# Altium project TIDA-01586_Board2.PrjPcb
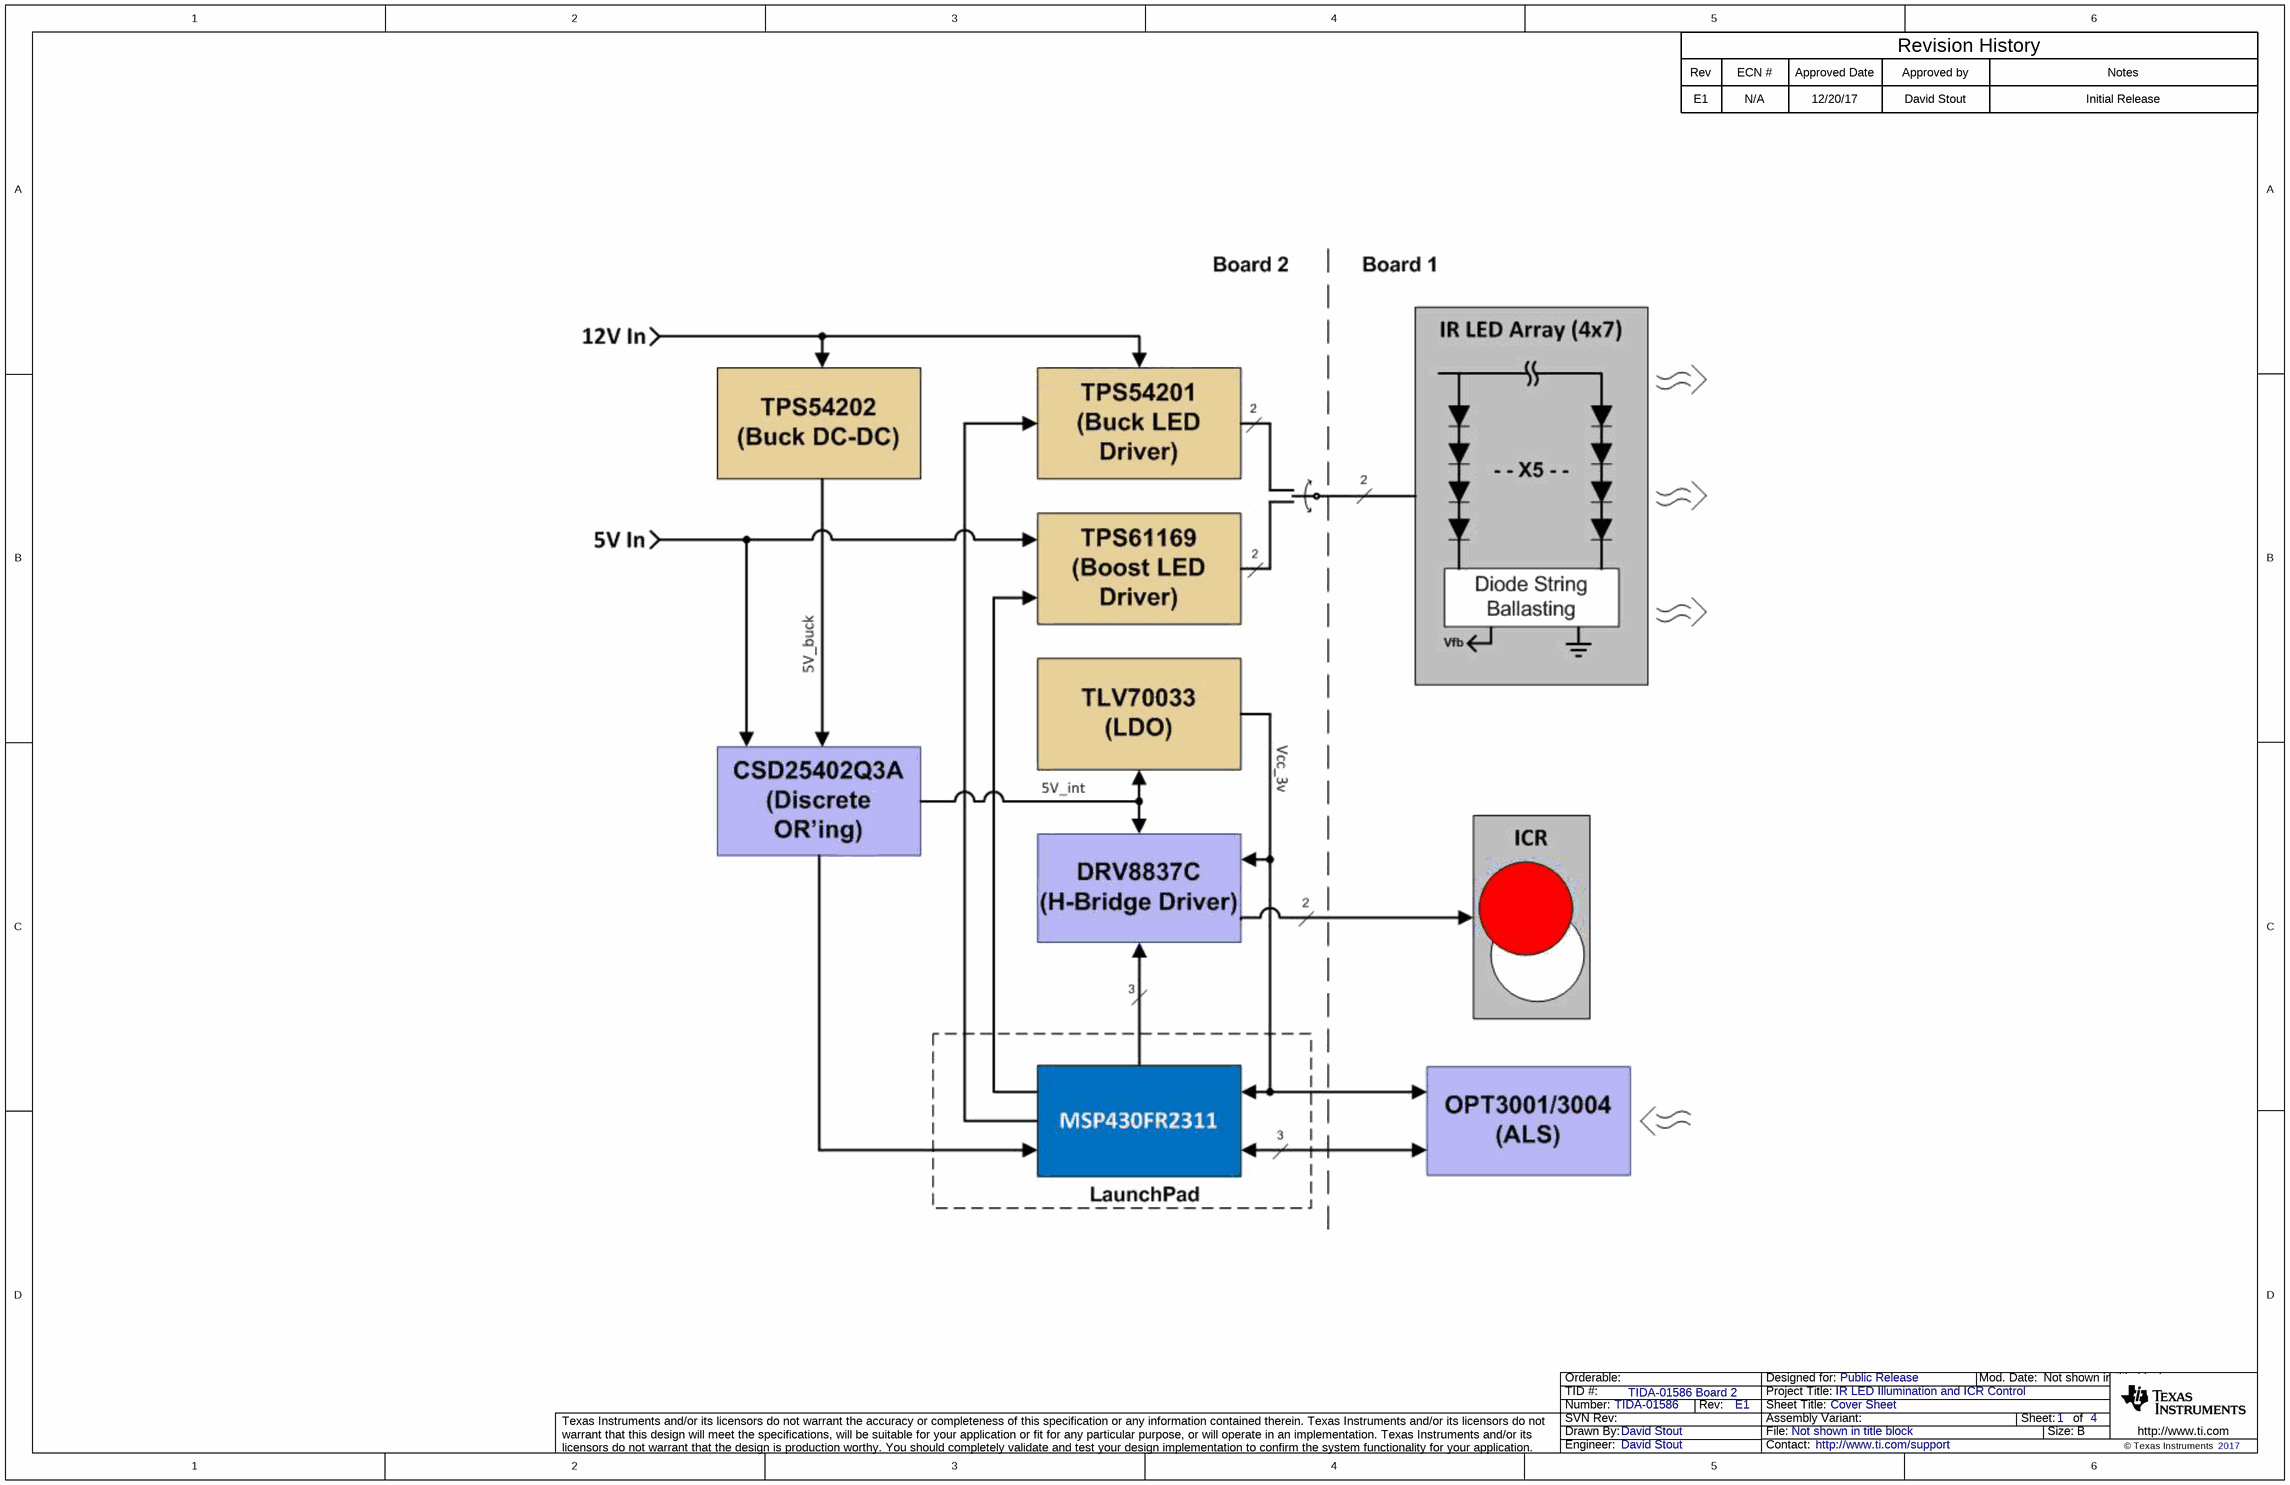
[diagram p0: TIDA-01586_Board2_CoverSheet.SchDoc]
CopyrightYear: 2017; PCB_Layout: Krypton Solutions; PCB_Rev: E1; PRJ_Customer: Public Release; PRJ_Engineer: David Stout; PRJ_Number: TIDA-01586; PRJ_Title: IR LED Illumination and ICR Control; SCH_Rev: E1; TechSupport: http://www.ti.com/support; TID: TIDA-01586 Board 2
4 sheets, 118 parts. Net scope: global (net labels, ports and power ports of the same name join across sheets).
Board file: TIDA-01586_Board2.PcbDoc
Sheets:
  TIDA-01586_Board2_CoverSheet.SchDoc
  TIDA-01586_Board2_Power.SchDoc
  TIDA-01586_Board2_MCU_Drivers.SchDoc
  TIDA-01586_Board2_Hardware.SchDoc

## Sheet TIDA-01586_Board2_CoverSheet.SchDoc: Cover Sheet
size 431 x 279 mm; Date: Not shown in title block; ApprovedBy: Not shown in title block; CheckedBy: Not shown in title block; Author: Not shown in title block; CompanyName: Not shown in title block; DrawnBy: David Stout; Engineer: Not shown in title block; Organization: Not shown in title block; Address1: Not shown in title block; Address2: Not shown in title block; Address3: Not shown in title block; Address4: Not shown in title block; DocumentNumber: 1; Revision: Use project parameter SCH_Rev; SheetNumber: 1; SheetTotal: 4; PageSetup: Record=PageOptions¦CenterHorizontal=True¦CenterVertical=True¦PrintScale=1.00¦XCorrection=1.00¦YCorrection=1.00¦PrintKind=0¦BorderSize=5000000¦LeftOffset=0¦BottomOffset=0¦Orientation=2¦PaperLength=1000¦PaperWidth=1000¦Scale=100¦PaperSource=15¦PrintQuality=600¦MediaType=1¦DitherType=10¦PaperKind=Letter¦PrintScaleMode=1

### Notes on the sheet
- Rev
- E1
- ECN #
- N/A
- Approved Date
- 12/20/17
- Approved by
- David Stout
- Revision History
- Notes
- Initial Release

## Sheet TIDA-01586_Board2_Power.SchDoc: Power Supply Section
size 431 x 279 mm; Date: Not shown in title block; ApprovedBy: Not shown in title block; CheckedBy: Not shown in title block; Author: Not shown in title block; CompanyName: Not shown in title block; DrawnBy: David Stout; Engineer: Not shown in title block; Organization: Not shown in title block; Address1: Not shown in title block; Address2: Not shown in title block; Address3: Not shown in title block; Address4: Not shown in title block; DocumentNumber: 1; Revision: Use project parameter SCH_Rev; SheetNumber: 2; SheetTotal: 4; PageSetup: Record=PageOptions¦CenterHorizontal=True¦CenterVertical=True¦PrintScale=1.00¦XCorrection=1.00¦YCorrection=1.00¦PrintKind=0¦BorderSize=5000000¦LeftOffset=0¦BottomOffset=0¦Orientation=2¦PaperLength=1000¦PaperWidth=1000¦Scale=100¦PaperSource=15¦PrintQuality=600¦MediaType=1¦DitherType=10¦PaperKind=Letter¦PrintScaleMode=1
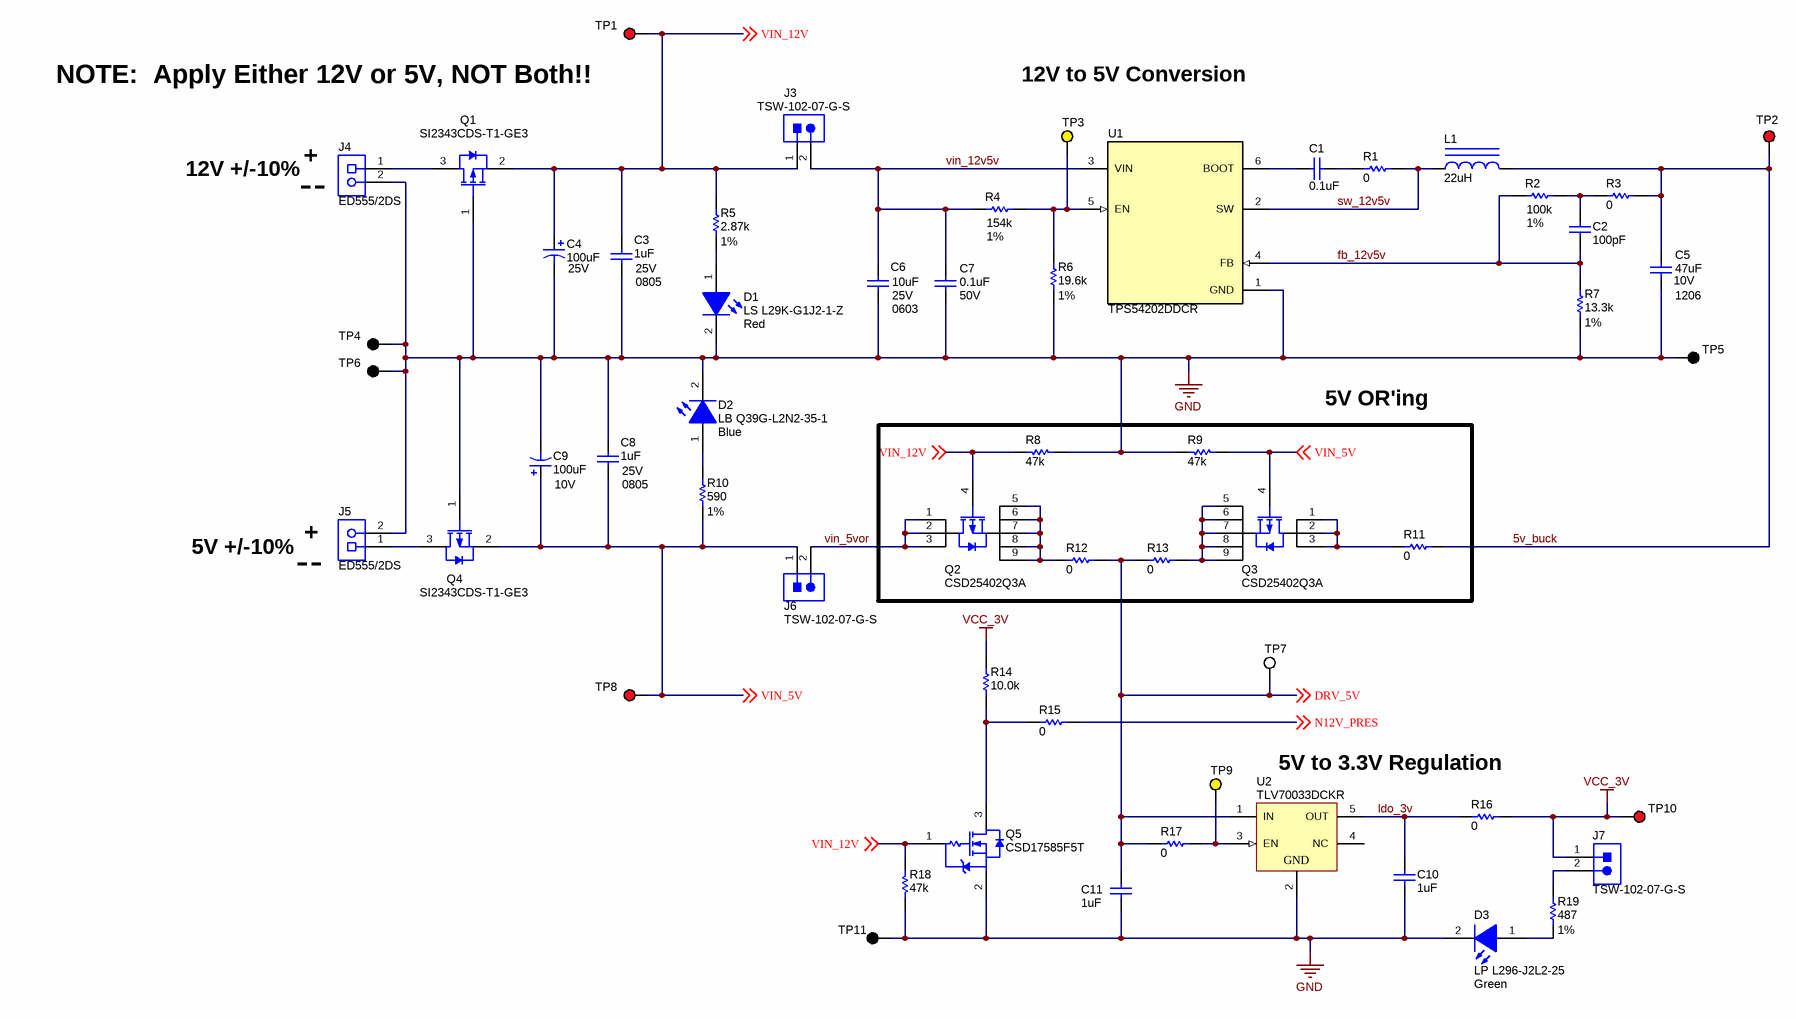
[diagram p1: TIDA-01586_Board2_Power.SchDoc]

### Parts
C1  ValueDisplayed: 0.1uF  [0402]  (hidden comment: GRM155R71A104KA01D)
C2  ValueDisplayed: 100pF  [0603]  (hidden comment: GRM1885C1H101JA01D)
C3  Cap_Case: 0805  VDC_V: 25V  ValueDisplayed: 1uF  [0805_HV]  (hidden comment: C0805C105K3RACTU)
C4  VDC_V: 25V  ValueDisplayed: 100uF  [7361-38]  (hidden comment: TPSV107K025R0100)
C5  Cap_Case: 1206  VDC_V: 10V  ValueDisplayed: 47uF  [1206_180]  (hidden comment: GRT31CR61A476KE13L)
C6  VDC_V: 25V  ValueDisplayed: 10uF  [0603]  (hidden comment: GRM188R61E106MA73D)
C7  VDC_V: 50V  ValueDisplayed: 0.1uF  [0402]  (hidden comment: C1005X7R1H104K050BB)
C8  Cap_Case: 0805  VDC_V: 25V  ValueDisplayed: 1uF  [0805_HV]  (hidden comment: C0805C105K3RACTU)
C9  VDC_V: 10V  ValueDisplayed: 100uF  [7343-31]  (hidden comment: TPSD107K010R0100)
C10  ValueDisplayed: 1uF  [0402]  (hidden comment: GRM155R61A105ME15D)
C11  ValueDisplayed: 1uF  [0402]  (hidden comment: GRM155R61A105ME15D)
D1  LS L29K-G1J2-1-Z  value Red  [LS L29K_Red]
D2  LB Q39G-L2N2-35-1  value Blue  [LB Q39G_BLUE]
D3  LP L296-J2L2-25  value Green  [LPL296_Green]
J3  TSW-102-07-G-S  [TSW-102-07-G-S]
J4  ED555/2DS  [TERM_BLK_ED555-2DS]
J5  ED555/2DS  [TERM_BLK_ED555-2DS]
J6  TSW-102-07-G-S  [TSW-102-07-G-S]
J7  TSW-102-07-G-S  [TSW-102-07-G-S]
L1  ValueDisplayed: 22uH  [SRR0745A]  (hidden comment: SRR0745A-220M)
Q1  SI2343CDS-T1-GE3  [SOT-23]
Q2  CSD25402Q3A  [DNH0008A]
Q3  CSD25402Q3A  [DNH0008A]
Q4  SI2343CDS-T1-GE3  [SOT-23]
Q5  CSD17585F5T  [YJK0003A]
R1  ValueDisplayed: 0  [0402]  (hidden comment: RC0402JR-070RL)
R2  Value1: 1%  ValueDisplayed: 100k  [0603]  (hidden comment: RC0603FR-07100KL)
R3  ValueDisplayed: 0  [0603]  (hidden comment: RC0603JR-070RL)
R4  Value1: 1%  ValueDisplayed: 154k  [0603]  (hidden comment: RC0603FR-07154KL)
R5  Value1: 1%  ValueDisplayed: 2.87k  [0603]  (hidden comment: CRCW06032K87FKEA)
R6  Value1: 1%  ValueDisplayed: 19.6k  [0603]  (hidden comment: RC0603FR-0719K6L)
R7  Value1: 1%  ValueDisplayed: 13.3k  [0603]  (hidden comment: RC0603FR-0713K3L)
R8  ValueDisplayed: 47k  [0603]  (hidden comment: RC0603JR-0747KL)
R9  ValueDisplayed: 47k  [0603]  (hidden comment: RC0603JR-0747KL)
R10  Value1: 1%  ValueDisplayed: 590  [0603]  (hidden comment: CRCW0603590RFKEA)
R11  ValueDisplayed: 0  [0603]  (hidden comment: RC0603JR-070RL)
R12  ValueDisplayed: 0  [0603]  (hidden comment: RC0603JR-070RL)
R13  ValueDisplayed: 0  [0603]  (hidden comment: RC0603JR-070RL)
R14  ValueDisplayed: 10.0k  [0603]  (hidden comment: RC0603FR-0710KL)
R15  ValueDisplayed: 0  [0603]  (hidden comment: RC0603JR-070RL)
R16  ValueDisplayed: 0  [0603]  (hidden comment: RC0603JR-070RL)
R17  ValueDisplayed: 0  [0603]  (hidden comment: RC0603JR-070RL)
R18  ValueDisplayed: 47k  [0603]  (hidden comment: RC0603JR-0747KL)
R19  Value1: 1%  ValueDisplayed: 487  [0603]  (hidden comment: CRCW0603487RFKEA)
TP1  5000  [Keystone5000]  (value not drawn)
TP2  5000  [Keystone5000]  (value not drawn)
TP3  5004  [Keystone5004]  (value not drawn)
TP4  5001  [Keystone5001]  (value not drawn)
TP5  5001  [Keystone5001]  (value not drawn)
TP6  5001  [Keystone5001]  (value not drawn)
TP7  5002  [Keystone5002]  (value not drawn)
TP8  5000  [Keystone5000]  (value not drawn)
TP9  5004  [Keystone5004]  (value not drawn)
TP10  5000  [Keystone5000]  (value not drawn)
TP11  5001  [Keystone5001]  (value not drawn)
U1  TPS54202DDCR  [DDC0006A_N]
U2  TLV70033DCKR  [DCK0005A_N]

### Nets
GND: C3.2 C4.2(-) C5.2 C6.2 C7.2 C8.1 C9.2(-) C10.1 C11.2 D1.2(K) D2.2(K) D3.2(K) J4.2 J5.2 Q1.1(G) Q4.1(G) Q5.2(S) R6.1 R7.1 R8.1 R9.1 R18.2 TP4.1 TP5.1 TP6.1 TP11.1 U1.1(GND) U2.2(GND)
VCC_3V: J7.1 R14.2 R16.2 TP10.1
5v_buck: C5.1 L1.2 R3.1 R11.2 TP2.1
DRV_5V: C11.1 R12.2 R13.1 R17.1 TP7.1 U2.1(IN) ; off-sheet DRV_5V
fb_12v5v: C2.2 R2.2 R7.2 U1.4(FB)
ldo_3v: C10.2 R16.1 U2.5(OUT)
N12V_PRES: R15.2 ; off-sheet N12V_PRES
sw_12v5v: L1.1 R1.2 U1.2(SW)
VIN_5V: C8.2 C9.1(+) J6.1 Q3.4(G) Q4.2(S) R9.2 R10.2 TP8.1 ; off-sheet VIN_5V
vin_5vor: J6.2 Q2.1(D) Q2.2(D) Q2.3(D)
VIN_12V: C3.1 C4.1(+) J3.1 Q1.2(S) Q2.4(G) Q5.1(G) R5.2 R8.2 R18.1 TP1.1 ; off-sheet VIN_12V
vin_12v5v: C6.1 C7.1 J3.2 R4.1 U1.3(VIN)
NetC1_1: C1.1 U1.6(BOOT)
NetC1_2: C1.2 R1.1
NetC2_1: C2.1 R2.1 R3.2
NetD1_1: D1.1(A) R5.1
NetD2_1: D2.1(A) R10.1
NetD3_1: D3.1(A) R19.1
NetJ4_1: J4.1 Q1.3(D)
NetJ5_1: J5.1 Q4.3(D)
NetJ7_2: J7.2 R19.2
NetQ2_5: Q2.5(S) Q2.6(S) Q2.7(S) Q2.8(S) Q2.9(S) R12.1
NetQ3_1: Q3.1(D) Q3.2(D) Q3.3(D) R11.1
NetQ3_5: Q3.5(S) Q3.6(S) Q3.7(S) Q3.8(S) Q3.9(S) R13.2
NetQ5_3: Q5.3(D) R14.1 R15.1
NetR4_2: R4.2 R6.2 TP3.1 U1.5(EN)
NetR17_2: R17.2 TP9.1 U2.3(EN)

Not connected (* = marked no-connect by the designer): U2 4(NC)

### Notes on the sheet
- (near TP1) NOTE:  Apply Either 12V or 5V, NOT Both!!
- 12V to 5V Conversion
- 12V +/-10%
- (near J4) ¦   +
- 5V OR'ing
- 5V +/-10%
- (near J5) +   ¦
- 5V to 3.3V Regulation

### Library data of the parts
C1 = CMP-0006629-2: CAP, CERM, 0.1 uF, 10 V, +/- 10%, X7R, 0402; Manufacturer: MuRata; TaMin_C: -55°C; Polarized: N; SizeAreaWB_mm2: 3; Value1: Unknown; U/M: EA; Value: 0.1uF; TaMax_C: 125°C; SizeZ_mm: 0.6; SizeX_mm: 1; SizeY_mm: 0.5; Value2: 10V; Cap_F: 100nF; AEC Category: Q200
C2 = CMP-0007171-4: CAP, CERM, 100 pF, 50 V, +/- 5%, C0G/NP0, 0603; Manufacturer: MuRata; TaMin_C: -55°C; Polarized: N; SizeAreaWB_mm2: 4.68; Value1: Unknown; U/M: EA; Value: 100pF; TaMax_C: 125°C; SizeZ_mm: 1; SizeX_mm: 1.6; SizeY_mm: 0.8; Value2: 50V; SizeArea_mm2: 1.28; AEC Category: Q200
C3 C8 = CMP-0007728-2: CAP, CERM, 1 uF, 25 V, +/- 10%, X7R, 0805; Manufacturer: Kemet; TaMin_C: -55°C; Polarized: N; SizeAreaWB_mm2: 6.75; Value1: Unknown; U/M: EA; Value: 1uF; TaMax_C: 125°C; SizeZ_mm: 1.45; SizeX_mm: 2; SizeY_mm: 1.25; SizeArea_mm2: 2.5; Cap_F: 1µF; AEC Category: Q200
C4 = CMP-0012041-2: CAP, TA, 100 uF, 25 V, +/- 10%, 0.1 ohm, SMD; Manufacturer: AVX; TaMin_C: -55°C; ESR_ohm: 1d; Polarized: Y; SizeAreaWB_mm2: 75.33; Value1: 0.1 ohm; U/M: EA; Value: 100uF; TaMax_C: 125°C; SizeZ_mm: 3.8; SizeX_mm: 7.3; SizeY_mm: 6.1; SizeArea_mm2: 44.53; CompType: Capacitor; Cap_F: 100µF; IRMS_A: 1.423A; AEC Category: Q200
C5 = CMP-0009013-2: CAP, CERM, 47 uF, 10 V, +/- 10%, X5R, AEC-Q200 Grade 1, 1206; Manufacturer: MuRata; TaMin_C: -55°C; Polarized: N; SizeAreaWB_mm2: 10.92; Value1: Unknown; U/M: EA; Value: 47uF; TaMax_C: 85°C; SizeZ_mm: 1.8; SizeX_mm: 3.2; SizeY_mm: 1.6; SizeArea_mm2: 5.12; AEC Qualified: Y; Cap_F: 47µF; AEC Grade: 1; AEC Category: Q200
C6 = CMP-0007344-5: CAP, CERM, 10 uF, 25 V, +/- 20%, X5R, 0603; Manufacturer: MuRata; TaMin_C: -55°C; Polarized: N; SizeAreaWB_mm2: 4.68; Value1: Unknown; U/M: EA; Value: 10uF; TaMax_C: 85°C; SizeZ_mm: 1; SizeX_mm: 1.6; SizeY_mm: 0.8; SizeArea_mm2: 1.28; Cap_F: 10µF; AEC Category: Q200
C7 = CMP-0006297-2: CAP, CERM, 0.1 uF, 50 V, +/- 10%, X7R, 0402; Manufacturer: TDK; TaMin_C: -55°C; ESR_ohm: 0.039064; Polarized: N; SizeAreaWB_mm2: 3; Value1: 0.039064 ohm; U/M: EA; Value: 0.1uF; TaMax_C: 125°C; SizeZ_mm: 0.6; SizeX_mm: 1; SizeY_mm: 0.5; Cap_F: 100nF; IRMS_A: 8.14669dA; AEC Category: Q200
C9 = CMP-0011859-2: CAP, TA, 100 uF, 10 V, +/- 10%, 0.1 ohm, SMD; Manufacturer: AVX; TaMin_C: -55°C; ESR_ohm: 1d; Polarized: Y; SizeAreaWB_mm2: 58.59; Value1: 0.1 ohm; U/M: EA; Value: 100uF; TaMax_C: 125°C; SizeZ_mm: 3.1; SizeX_mm: 7.3; SizeY_mm: 4.3; Cap_Case: D; SizeArea_mm2: 31.39; CompType: Capacitor; Cap_F: 100µF; IRMS_A: 1.102A; AEC Category: Q200
C10 C11 = CMP-0064927-2: CAP, CERM, 1 uF, 10 V,+/- 20%, X5R, 0402; Manufacturer: MuRata; TaMin_C: -55°C; Polarized: N; SizeAreaWB_mm2: 3; Value1: Unknown; U/M: EA; Value: 1uF; TaMax_C: 85°C; SizeZ_mm: 0.6; SizeX_mm: 1; SizeY_mm: 0.5; Value2: 10V; CompType: Capacitor; Cap_F: 1µF; AEC Category: Q200
D1 = CMP-0002902-1: LED, Red, SMD; Manufacturer: OSRAM; Io_A: 20mA; Vr_V: 12V; Tjmax_C: 110°C; Value1: W; U/M: EA; Angle: 160; Vf_V: 1.8V
D2 = CMP-0002849-1: LED, Blue, SMD; Manufacturer: OSRAM; Io_A: 1.5dA; Tjmax_C: 95°C; Value1: W; U/M: EA; Vf_V: 2.85V
D3 = CMP-0077694-1: LED, Green, SMD; Manufacturer: OSRAM; Tjmax_C: 110°C; SizeAreaWB_mm2: 4.86; Vr_V: 12V; SizeArea_mm2: 1.36; Angle: 160.0; Ir_A: 10nA; SizeZ_mm: 0.67; Io_A: 20mA; Vf_V: 2V; SizeY_mm: 0.8; U/M: EA; Value1: W; SizeX_mm: 1.7
J3 J6 J7 = CMP-0075405-2: Header, 100mil, 2x1, Gold, TH; Manufacturer: Samtec; Pitch_mm: 2.54; Cert_VDE: N; Gender: Male; Cert_CSA: Y; Voltage_V: 550V; Green_REACh: Passed; Current_A: 6.3A; Green_Lifecycle: Active; Row_Count: 1
J4 J5 = CMP-0074913-1: Terminal Block, 3.5mm Pitch, 2x1, TH; Manufacturer: On-Shore Technology; Cert_VDE: Y; CNHeader: False; Current_A: 6A; Green_Lifecycle: Active; Shrouded: N; Gender: Female; Green_REACh: Passed; Voltage_V: 150V; Row_Count: 1; Pitch_mm: 3.5; ContactFinish: Brass; CT: True
L1 = CMP-0057729-2: Inductor, Shielded Drum Core, Ferrite, 22 uH, 1.65 A, 0.096 ohm, AEC-Q200 Grade 1, SMD; Manufacturer: Bourns; Isat: 1.75A @ 25% inductance drop; Irms: 1.65A @ 40C rise; SizeAreaWB_mm2: 86.49; DCR_ohm: 0.096; Value: 22uH; Imax_A: 1.65A; SizeZ_mm: 4.7; SizeX_mm: 7.3; SizeArea_mm2: 53.29; Ind_H: 22µH; AEC Qualified: Y; AEC Grade: 1; AEC Category: Q200
Q1 Q4 = CMP-0000096-2: MOSFET, P-CH, -30 V, -5.9 A, SOT-23; Alternate Manufacturer: None; Manufacturer: Vishay-Siliconix; SizeZ_mm: 1.1; ChType: P; Value2: 13.6 nC; Value1: 0.07; VdsMax_V: -30V; SizeX_mm: 2.5; SizeY_mm: 3; Vgs_V: -20V; Value: -30V; Rdson45_ohm: 0.075; SizeArea_mm2: 7.5; AEC Category: Q101; IdsMax_A: -5.9A; SizeAreaWB_mm2: 14; U/M: EA; QgTyp_nC: 13.6
Q2 Q3 = CMP-0000025-2: MOSFET, P-CH, -20 V, -15 A, DNH0008A (VSONP-8); Alternate Manufacturer: None; Manufacturer: Texas Instruments; SizeZ_mm: 0.9; ChType: P; Value2: 7.5 nC; Value1: 0.007; VdsMax_V: -20V; SizeX_mm: 3.3; Vgs_V: -12V; Value: -20V; Rdson45_ohm: 7.7m; SizeArea_mm2: 10.89; AEC Category: Q101; IdsMax_A: -15A; SizeAreaWB_mm2: 18.49; U/M: EA; QgTyp_nC: 7.5
Q5 = CMP-0067551-1: MOSFET, N-CH, 30 V, 5.9 A, YJK0003A (PICOSTAR-3); Alternate Manufacturer: None; Manufacturer: Texas Instruments; Rdson45_ohm: 0.033; QgTyp_nC: 1.9; SizeAreaWB_mm2: 4.3077; Vgs_V: 20V; Value1: 0.033 ohm; VdsMax_V: 30V; U/M: EA; Value: 30V; IdsMax_A: 5.9A; SizeZ_mm: 0.35; SizeX_mm: 1.49; SizeY_mm: 0.73; Value2: 1.9 nC; SizeArea_mm2: 1.0877; ChType: N; AEC Category: Q101
R1 = CMP-0027004-2: RES, 0, 5%, 0.063 W, 0402; Manufacturer: Yageo America; Power_W: 63mW; TempCo: 200 ppm/C; Value_Code: 0000; U/M: EA; Value: 0; EIA_Code: E24; SizeX_mm: 1; SizeY_mm: 0.5; SizeZ_mm: 0.6; Value2: 0.063W; VDC_V: 50V; AEC Category: Q200
R2 = CMP-0022735-3: RES, 100 k, 1%, 0.1 W, 0603; Manufacturer: Yageo America; Power_W: 100mW; TempCo: 200 ppm/C; U/M: EA; Value: 100k; EIA_Code: E96; SizeX_mm: 1.6; SizeY_mm: 0.8; SizeZ_mm: 1; Value2: 0.1W; SizeArea_mm2: 1.28; VDC_V: 150V; AEC Category: Q200
R3 R11-R13 R15-R17 = CMP-0025885-3: RES, 0, 5%, 0.1 W, 0603; Manufacturer: Yageo America; Power_W: 100mW; TempCo: 200 ppm/C; Value_Code: 0000; U/M: EA; Value: 0; EIA_Code: E24; SizeX_mm: 1.6; SizeZ_mm: 1; Value2: 0.1W; SizeArea_mm2: 1.28; VDC_V: 50V; AEC Category: Q200; SizeY_mm: 0.8
R4 = CMP-0022810-2: RES, 154 k, 1%, 0.1 W, 0603; Manufacturer: Yageo America; Power_W: 100mW; TempCo: 200 ppm/C; U/M: EA; Value: 154k; EIA_Code: E96; SizeX_mm: 1.6; SizeY_mm: 0.8; SizeZ_mm: 1; Value2: 0.1W; SizeArea_mm2: 1.28; VDC_V: 150V; AEC Category: Q200
R5 = CMP-0022283-4: RES, 2.87 k, 1%, 0.1 W, AEC-Q200 Grade 0, 0603; Manufacturer: Vishay-Dale; Power_W: 100mW; TempCo: 100 ppm/C; Value_Code: 2k87; Value: 2.87k; EIA_Code: E96; SizeX_mm: 1.6; SizeY_mm: 0.8; SizeZ_mm: 1; Value2: 0.1W; SizeArea_mm2: 1.28; AEC Qualified: Y; VDC_V: 75V; AEC Category: Q200; AEC Grade: 0
R6 = CMP-0022861-3: RES, 19.6 k, 1%, 0.1 W, 0603; Manufacturer: Yageo America; Power_W: 100mW; TempCo: 200 ppm/C; Value_Code: 19k6; U/M: EA; Value: 19.6k; EIA_Code: E96; SizeX_mm: 1.6; SizeY_mm: 0.8; SizeZ_mm: 1; Value2: 0.1W; SizeArea_mm2: 1.28; VDC_V: 150V; AEC Category: Q200
R7 = CMP-0022790-3: RES, 13.3 k, 1%, 0.1 W, 0603; Manufacturer: Yageo America; Power_W: 100mW; TempCo: 200 ppm/C; Value_Code: 13k3; U/M: EA; Value: 13.3k; EIA_Code: E96; SizeX_mm: 1.6; SizeY_mm: 0.8; SizeZ_mm: 1; Value2: 0.1W; SizeArea_mm2: 1.28; VDC_V: 150V; AEC Category: Q200
R8 R9 R18 = CMP-0025925-3: RES, 47 k, 5%, 0.1 W, 0603; Manufacturer: Yageo America; Power_W: 100mW; TempCo: 100 ppm/C; Value_Code: 47k0; U/M: EA; Value: 47k; EIA_Code: E24; SizeX_mm: 1.6; SizeY_mm: 0.8; SizeZ_mm: 1; Value2: 0.1W; SizeArea_mm2: 1.28; VDC_V: 50V; AEC Category: Q200
R10 = CMP-0022506-5: RES, 590, 1%, 0.1 W, AEC-Q200 Grade 0, 0603; Manufacturer: Vishay-Dale; Power_W: 100mW; TempCo: 100 ppm/C; Value_Code: 590R; Value: 590; EIA_Code: E96; SizeX_mm: 1.6; SizeY_mm: 0.8; SizeZ_mm: 1; Value2: 0.1W; SizeArea_mm2: 1.28; AEC Qualified: Y; VDC_V: 75V; AEC Category: Q200; AEC Grade: 0
R14 = CMP-0022746-3: RES, 10.0 k, 1%, 0.1 W, 0603; Manufacturer: Yageo America; Power_W: 100mW; TempCo: 200 ppm/C; Value_Code: 10k0; U/M: EA; Value: 10.0k; EIA_Code: E96; Res_ohm: 10k; SizeX_mm: 1.6; SizeY_mm: 0.8; SizeZ_mm: 1; Value2: 0.1W; SizeArea_mm2: 1.28; VDC_V: 150V; AEC Category: Q200
R19 = CMP-0022442-5: RES, 487, 1%, 0.1 W, AEC-Q200 Grade 0, 0603; Manufacturer: Vishay-Dale; Power_W: 100mW; TempCo: 100 ppm/C; Value_Code: 487R; Value: 487; EIA_Code: E96; SizeX_mm: 1.6; SizeY_mm: 0.8; SizeZ_mm: 1; Value2: 0.1W; SizeArea_mm2: 1.28; AEC Qualified: Y; VDC_V: 75V; AEC Category: Q200; AEC Grade: 0
TP1 TP2 TP8 TP10 = CMP-0055137-1: Test Point, Miniature, Red, TH; Manufacturer: Keystone; CNHeader: FALSE; Green_Lifecycle: Active; Green_REACh: Passed; ContactFinish: Silver; CT: TRUE
TP3 TP9 = CMP-0055141-1: Test Point, Miniature, Yellow, TH; Manufacturer: Keystone; CNHeader: FALSE; Green_Lifecycle: Active; Green_REACh: Passed; ContactFinish: Silver; CT: TRUE
TP4-TP6 TP11 = CMP-0055138-1: Test Point, Miniature, Black, TH; Manufacturer: Keystone; CNHeader: FALSE; Green_Lifecycle: Active; Green_REACh: Passed; ContactFinish: Silver; CT: TRUE
TP7 = CMP-0055139-1: Test Point, Miniature, White, TH; Manufacturer: Keystone; CNHeader: FALSE; Green_Lifecycle: Active; Green_REACh: Passed; ContactFinish: Silver; CT: TRUE
U1 = CMP-0073969-2: 4.5V to 28V Input, 2A Output, EMI Friendly Synchronous Step-Down Converter, DDC0006A (SOT-23-T-6); Alternate PartNumber: TPS54202DDCT; Manufacturer: Texas Instruments; SizeZ_mm: 0.87; SizeX_mm: 1.65; SizeY_mm: 2.95; SizeArea_mm2: 4.8675; CompType: IC; U/M: EA; SizeAreaWB_mm2: 10.4675
U2 = CMP-0035682-1: Single Output LDO, 200 mA, Fixed 3.3 V Output, 2 to 5.5 V Input, with Low IQ, 5-pin SC70 (DCK), -40 to 125 degC, Green (RoHS & no Sb/Br); Manufacturer: Texas Instruments; Vin(Max)(V): 5.5; Vout Adj(Min)(V): 3.3; Vdo(Typ)(mV): 175; Vin(Min)(V): 2; Iout(Max)(A): 0.2; SubFamily: Single Channel LDO; Iq(Typ)(mA): 0.03

## Sheet TIDA-01586_Board2_MCU_Drivers.SchDoc: LED and Motor Drivers / MCU Interface
size 431 x 279 mm; Date: Not shown in title block; ApprovedBy: Not shown in title block; CheckedBy: Not shown in title block; Author: Not shown in title block; CompanyName: Not shown in title block; DrawnBy: David Stout; Engineer: Not shown in title block; Organization: Not shown in title block; Address1: Not shown in title block; Address2: Not shown in title block; Address3: Not shown in title block; Address4: Not shown in title block; DocumentNumber: 1; Revision: Use project parameter SCH_Rev; SheetNumber: 3; SheetTotal: 4; PageSetup: Record=PageOptions¦CenterHorizontal=True¦CenterVertical=True¦PrintScale=1.00¦XCorrection=1.00¦YCorrection=1.00¦PrintKind=0¦BorderSize=5000000¦LeftOffset=0¦BottomOffset=0¦Orientation=2¦PaperLength=1000¦PaperWidth=1000¦Scale=100¦PaperSource=15¦PrintQuality=600¦MediaType=1¦DitherType=10¦PaperKind=Letter¦PrintScaleMode=1
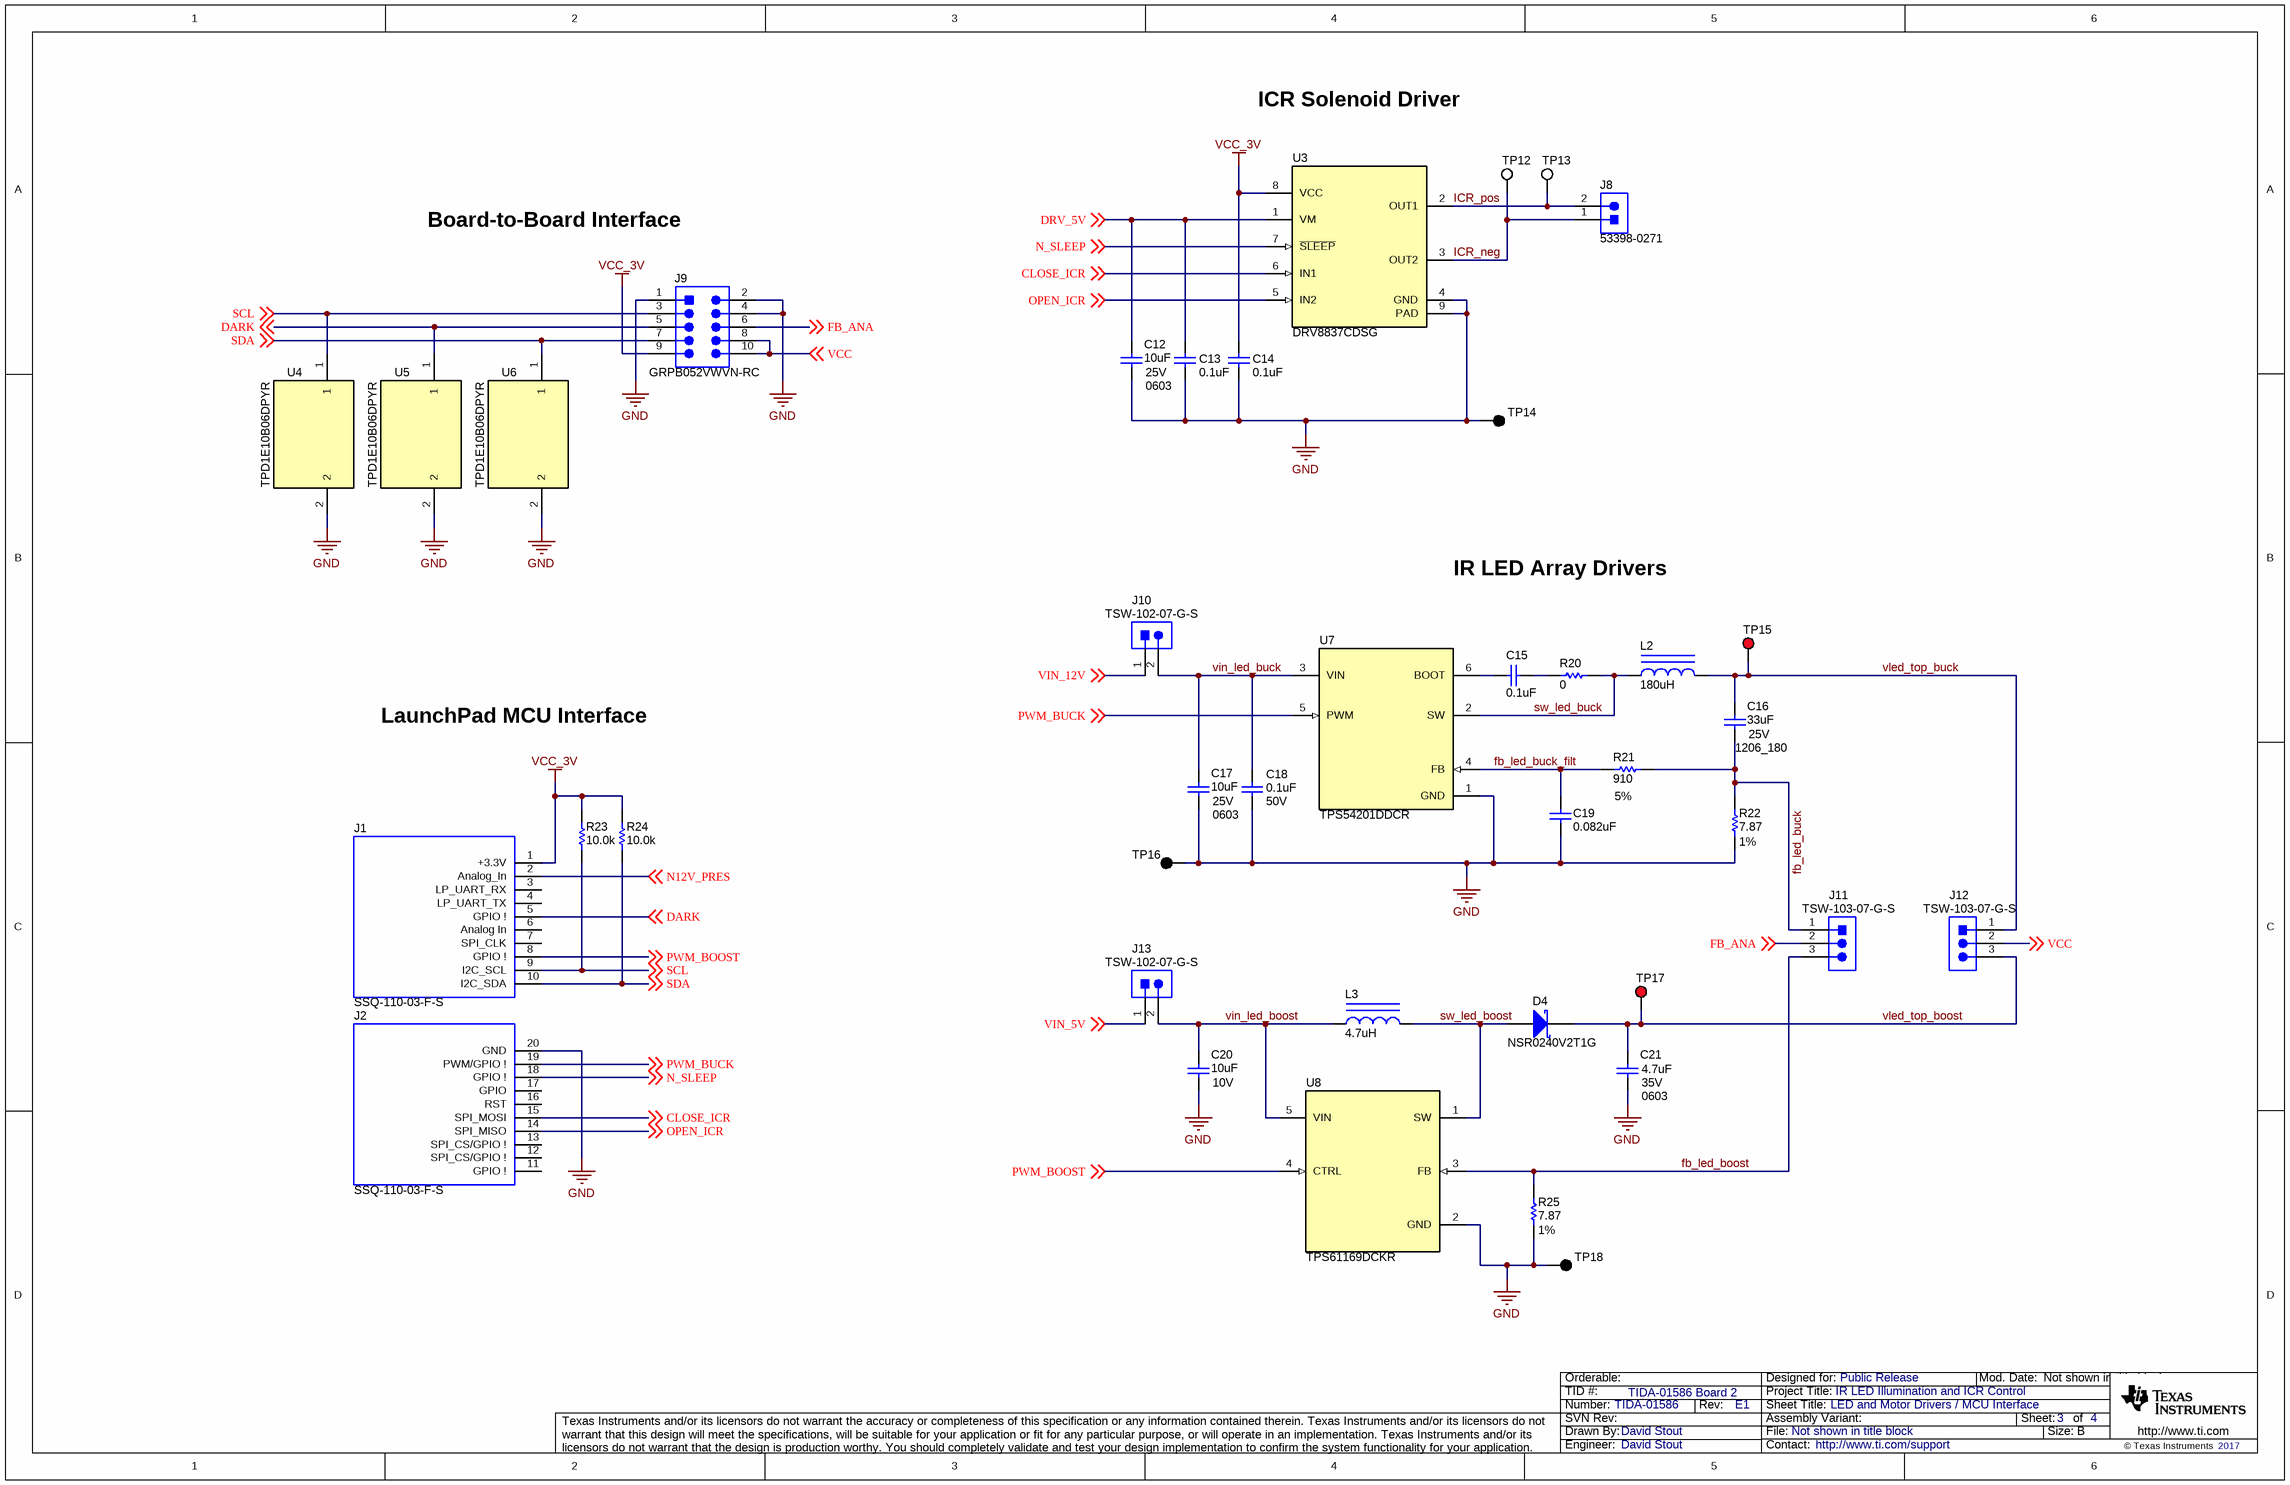
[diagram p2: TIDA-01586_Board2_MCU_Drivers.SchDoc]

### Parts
C12  VDC_V: 25V  ValueDisplayed: 10uF  [0603]  (hidden comment: GRM188R61E106MA73D)
C13  ValueDisplayed: 0.1uF  [0402]  (hidden comment: GRM155R71A104KA01D)
C14  ValueDisplayed: 0.1uF  [0402]  (hidden comment: GRM155R71A104KA01D)
C15  ValueDisplayed: 0.1uF  [0402]  (hidden comment: GRM155R71A104KA01D)
C16  VDC_V: 25V  ValueDisplayed: 33uF  [1206_180]  (hidden comment: C3216X5R1E336M160AC)
C17  VDC_V: 25V  ValueDisplayed: 10uF  [0603]  (hidden comment: GRM188R61E106MA73D)
C18  VDC_V: 50V  ValueDisplayed: 0.1uF  [0402]  (hidden comment: C1005X7R1H104K050BB)
C19  ValueDisplayed: 0.082uF  [0402]  (hidden comment: GRM155R71A823KA01D)
C20  VDC_V: 10V  ValueDisplayed: 10uF  [0402]  (hidden comment: CL05A106MP5NUNC)
C21  VDC_V: 35V  ValueDisplayed: 4.7uF  [0603]  (hidden comment: GRM188R6YA475KE15D)
D4  NSR0240V2T1G  [SOD-523]
J1  SSQ-110-03-F-S  [BoosterPack_20pin_J1]
J2  SSQ-110-03-F-S  [BoosterPack_20pin_J2]
J8  53398-0271  [0533980271]
J9  GRPB052VWVN-RC  [CONN_GRPB052VWVN-RC]
J10  TSW-102-07-G-S  [TSW-102-07-G-S]
J11  TSW-103-07-G-S  [TSW-103-07-G-S]
J12  TSW-103-07-G-S  [TSW-103-07-G-S]
J13  TSW-102-07-G-S  [TSW-102-07-G-S]
L2  ValueDisplayed: 180uH  [ELL6UH]  (hidden comment: ELL-6UH181M)
L3  ValueDisplayed: 4.7uH  [IFSC1515AH]  (hidden comment: IFSC1515AHER4R7M01)
R20  ValueDisplayed: 0  [0402]  (hidden comment: RC0402JR-070RL)
R21  Tolerance_%: 5%  ValueDisplayed: 910  [0402]  (hidden comment: CRCW0402910RJNED)
R22  Tolerance_%: 1%  ValueDisplayed: 7.87  [0402]  (hidden comment: CRCW04027R87FKED)
R23  ValueDisplayed: 10.0k  [0603]  (hidden comment: RC0603FR-0710KL)
R24  ValueDisplayed: 10.0k  [0603]  (hidden comment: RC0603FR-0710KL)
R25  Tolerance_%: 1%  ValueDisplayed: 7.87  [0402]  (hidden comment: CRCW04027R87FKED)
TP12  5002  [Keystone5002]  (value not drawn)
TP13  5002  [Keystone5002]  (value not drawn)
TP14  5001  [Keystone5001]  (value not drawn)
TP15  5000  [Keystone5000]  (value not drawn)
TP16  5001  [Keystone5001]  (value not drawn)
TP17  5000  [Keystone5000]  (value not drawn)
TP18  5001  [Keystone5001]  (value not drawn)
U3  DRV8837CDSG  [DSG0008A]
U4  TPD1E10B06DPYR  [DPY0002A]
U5  TPD1E10B06DPYR  [DPY0002A]
U6  TPD1E10B06DPYR  [DPY0002A]
U7  TPS54201DDCR  [DDC0006A_N]
U8  TPS61169DCKR  [DCK0005A_N]

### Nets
GND: C12.2 C13.2 C14.2 C17.2 C18.2 C19.2 C20.2 C21.2 J2.20(GND) J9.1 J9.2 J9.4 R22.1 R25.1 TP14.1 TP16.1 TP18.1 U3.4(GND) U3.9(PAD) U4.2 U5.2 U6.2 U7.1(GND) U8.2(GND)
VCC_3V: C14.1 J1.1(+3.3V) J9.9 R23.2 R24.2 U3.8(VCC)
CLOSE_ICR: J2.15(SPI_MOSI) U3.6(IN1) ; off-sheet CLOSE_ICR
DARK: J1.5(GPIO_!) J9.5 U5.1 ; off-sheet DARK
DRV_5V: C12.1 C13.1 U3.1(VM) ; off-sheet DRV_5V
FB_ANA: J9.6 J11.2 ; off-sheet FB_ANA
fb_led_boost: J11.3 R25.2 U8.3(FB)
fb_led_buck: C16.2 J11.1 R21.2 R22.2
fb_led_buck_filt: C19.1 R21.1 U7.4(FB)
ICR_neg: J8.1 TP12.1 U3.3(OUT2)
ICR_pos: J8.2 TP13.1 U3.2(OUT1)
N12V_PRES: J1.2(Analog_In) ; off-sheet N12V_PRES
N_SLEEP: J2.18(GPIO_!) U3.7(~{SLEEP}) ; off-sheet N_SLEEP
OPEN_ICR: J2.14(SPI_MISO) U3.5(IN2) ; off-sheet OPEN_ICR
PWM_BOOST: J1.8(GPIO_!) U8.4(CTRL) ; off-sheet PWM_BOOST
PWM_BUCK: J2.19(PWM/GPIO_!) U7.5(PWM) ; off-sheet PWM_BUCK
SCL: J1.9(I2C_SCL) J9.3 R23.1 U4.1 ; off-sheet SCL
SDA: J1.10(I2C_SDA) J9.7 R24.1 U6.1 ; off-sheet SDA
sw_led_boost: D4.2(A) L3.2 U8.1(SW)
sw_led_buck: L2.1 R20.2 U7.2(SW)
VCC: J9.8 J9.10 J12.2 ; off-sheet VCC
VIN_5V: J13.1 ; off-sheet VIN_5V
VIN_12V: J10.1 ; off-sheet VIN_12V
vin_led_boost: C20.1 J13.2 L3.1 U8.5(VIN)
vin_led_buck: C17.1 C18.1 J10.2 U7.3(VIN)
vled_top_boost: C21.1 D4.1(K) J12.3 TP17.1
vled_top_buck: C16.1 J12.1 L2.2 TP15.1
NetC15_1: C15.1 U7.6(BOOT)
NetC15_2: C15.2 R20.1

Not connected (* = marked no-connect by the designer): J1 3(LP_UART_RX) 4(LP_UART_TX) 6(Analog_In) 7(SPI_CLK); J2 11(GPIO_!) 12(SPI_CS/GPIO_!) 13(SPI_CS/GPIO_!) 16(RST) 17(GPIO)

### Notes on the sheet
- ICR Solenoid Driver
- Board-to-Board Interface
- IR LED Array Drivers
- LaunchPad MCU Interface

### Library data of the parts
C12 C17 = CMP-0007344-5: as C6 on sheet TIDA-01586_Board2_Power
C13-C15 = CMP-0006629-2: as C1 on sheet TIDA-01586_Board2_Power
C16 = CMP-0008655-2: CAP, CERM, 33 uF, 25 V, +/- 20%, X5R, 1206; Manufacturer: TDK; TaMin_C: -55°C; ESR_ohm: 2.648m; Polarized: N; SizeAreaWB_mm2: 10.92; Value1: 0.002648 ohm; U/M: EA; Value: 33uF; TaMax_C: 85°C; SizeZ_mm: 1.8; SizeX_mm: 3.2; SizeY_mm: 1.6; SizeArea_mm2: 5.12; Cap_F: 33µF; IRMS_A: 4.45864A; AEC Category: Q200
C18 = CMP-0006297-2: as C7 on sheet TIDA-01586_Board2_Power
C19 = CMP-0006637-2: CAP, CERM, 0.082 uF, 10 V, +/- 10%, X7R, 0402; Manufacturer: MuRata; TaMin_C: -55°C; Polarized: N; SizeAreaWB_mm2: 3; Value1: Unknown; U/M: EA; TaMax_C: 125°C; SizeZ_mm: 0.6; SizeX_mm: 1; SizeY_mm: 0.5; Value2: 10V; Cap_F: 82nF; AEC Category: Q200
C20 = CMP-0006339-2: CAP, CERM, 10 uF, 10 V, +/- 20%, X5R, 0402; Manufacturer: Samsung Electro-Mechanics; TaMin_C: -55°C; Polarized: N; SizeAreaWB_mm2: 3; Value1: Unknown; U/M: EA; Value: 10uF; TaMax_C: 85°C; SizeZ_mm: 0.6; SizeX_mm: 1; SizeY_mm: 0.5; Cap_F: 10µF; AEC Category: Q200
C21 = CMP-0007357-5: CAP, CERM, 4.7 uF, 35 V, +/- 10%, X5R, 0603; Manufacturer: MuRata; TaMin_C: -55°C; Polarized: N; SizeAreaWB_mm2: 4.68; Value1: Unknown; U/M: EA; Value: 4.7uF; TaMax_C: 85°C; SizeZ_mm: 1; SizeX_mm: 1.6; SizeY_mm: 0.8; SizeArea_mm2: 1.28; Cap_F: 4.7µF; AEC Category: Q200
D4 = CMP-0028616-2: Diode, Schottky, 40 V, 0.25 A, SOD-523; Manufacturer: ON Semiconductor; Io_A: 2.5dA; Green_Lifecycle: Active; SizeAreaWB_mm2: 5.13; Vr_V: 40V; Green_REACh: Passed; Value1: 0.25A; TJmax_C: 150°C; U/M: EA; Value: 40V; SizeZ_mm: 0.65; SizeX_mm: 1.7; SizeY_mm: 0.9; Vf_V: 7dV; Value2: 0.7V; SizeArea_mm2: 1.53; AEC Category: Q101
J1 = CMP-0003839-1: Receptacle, 2.54mm, 10x1, Gold, TH; Alternate PartNumber: SSHQ-110-S-08-G-LF; Manufacturer: Samtec; Alternate Manufacturer: Major League Electronics; Note: Booster Pack 20 pin J1
J2 = CMP-0078267-1: Receptacle, 2.54mm, 10x1, Gold, TH; Alternate PartNumber: SSHQ-110-S-08-G-LF; Manufacturer: Samtec; Alternate Manufacturer: Major League Electronics; Note: Booster Pack 20 pin J2
J8 = CMP-0055117-1: Plug, SMT, Vertical, 1.25mm, 1x2; Manufacturer: Molex; CT: FALSE; CompType: Header
J9 = CMP-0002340-2: Header, 50mil, 5x2, Gold, TH; Manufacturer: Sullins Connector Solutions; Green_Lifecycle: Not Set; Green_REACh: Incomplete; Cert_UL: Y; Current_A: 1A; Gender: Male; Pitch_mm: 1.27; Row_Count: 2; Shrouded: N
J10 J13 = CMP-0075405-2: as J3 on sheet TIDA-01586_Board2_Power
J11 J12 = CMP-0075407-2: Header, 100mil, 3x1, Gold, TH; Manufacturer: Samtec; Pitch_mm: 2.54; Cert_VDE: N; Gender: Male; Cert_CSA: Y; Voltage_V: 550V; Green_REACh: Passed; Current_A: 6.3A; Green_Lifecycle: Active; Row_Count: 1
L2 = CMP-0060108-1: Inductor, Shielded Drum Core, Ferrite, 180 uH, 0.47 A, 0.75 ohm, SMD; Manufacturer: Panasonic; Isat: 0.47A @ 20% inductance drop; Irms: 0.47A @ 45C rise; Green_Lifecycle: Not Set; SizeAreaWB_mm2: 67.2; DCR_ohm: 7.5d; Green_REACh: Incomplete; Value: 180uH; Imax_A: 4.7dA; SizeZ_mm: 5; SizeX_mm: 6.4; SizeY_mm: 6; Value2: 0.47A; SizeArea_mm2: 38.4; Ind_H: 180µH; AEC Category: Q200
L3 = CMP-0063230-1: Inductor, Shielded, Ferrite, 4.7 uH, 2 A, 0.09 ohm, SMD; Manufacturer: Vishay-Dale; Isat: 2A @ 20% inductance drop; Irms: 2.2A @ 40C rise; Green_Lifecycle: Not Set; SizeAreaWB_mm2: 25; DCR_ohm: 0.09; Green_REACh: Incomplete; Value: 4.7uH; Imax_A: 2A; SizeZ_mm: 1.9; SizeX_mm: 4; SizeArea_mm2: 16; Ind_H: 4.7µH; AEC Category: Q200
R20 = CMP-0027004-2: as R1 on sheet TIDA-01586_Board2_Power
R21 = CMP-0026986-3: RES, 910, 5%, 0.063 W, AEC-Q200 Grade 0, 0402; Manufacturer: Vishay-Dale; Power_W: 63mW; TempCo: 200 ppm/C; Value_Code: 910R; Value: 910; EIA_Code: E24; SizeX_mm: 1; SizeY_mm: 0.5; SizeZ_mm: 0.6; Value2: 0.063W; AEC Qualified: Y; VDC_V: 50V; AEC Category: Q200; AEC Grade: 0
R22 R25 = CMP-0026567-2: RES, 7.87, 1%, 0.063 W, AEC-Q200 Grade 0, 0402; Manufacturer: Vishay-Dale; Power_W: 63mW; TempCo: 100 ppm/C; Value_Code: 7R87; Value: 7.87; EIA_Code: E96; SizeX_mm: 1; SizeY_mm: 0.5; SizeZ_mm: 0.6; Value2: 0.063W; AEC Qualified: Y; VDC_V: 50V; AEC Category: Q200; AEC Grade: 0
R23 R24 = CMP-0022746-3: as R14 on sheet TIDA-01586_Board2_Power
TP12 TP13 = CMP-0055139-1: as TP7 on sheet TIDA-01586_Board2_Power
TP14 TP16 TP18 = CMP-0055138-1: as TP4 on sheet TIDA-01586_Board2_Power
TP15 TP17 = CMP-0055137-1: as TP1 on sheet TIDA-01586_Board2_Power
U3 = CMP-0013449-3: 1-A Low-Voltage H-Bridge Driver, DSG0008A (WSON-8); Manufacturer: Texas Instruments; SizeZ_mm: 0.8; SizeX_mm: 2; SizeArea_mm2: 4; CompType: IC; U/M: EA; SizeAreaWB_mm2: 9
U4-U6 = CMP-0043093-1: ESD in 0402 Package with 10 pF Capacitance and 6 V Breakdown, 1 Channel, -40 to +125 degC, 2-pin X2SON (DPY), Green (RoHS & no Sb/Br); Manufacturer: Texas Instruments; SubFamily: ESD Solution; IEC 61000-4-2 Air-Gap(+/- kV): 30; Eco-Plan: TBD; IO Capacitance(Typ)(pF): 10; Breakdown Voltage(Min)(V): 6
U7 = CMP-0013279-3: 4.5V TO 28V INPUT VOLTAGE, 1.5A OUTPUT CURRENT, SYNCHRONOUS BUCK WLED Driver, DDC0006A (SOT-6); Alternate PartNumber: TPS54201DDCT; Manufacturer: Texas Instruments; SizeZ_mm: 0.87; SizeX_mm: 1.65; SizeY_mm: 2.95; SizeArea_mm2: 4.8675; CompType: IC; U/M: EA; SizeAreaWB_mm2: 10.4675
U8 = CMP-0073719-1: TPS61169 38-V High-Current Boost WLED Driver, DCK0005A (SOT-SC70-5); Alternate Manufacturer: Texas Instruments; Green_Lifecycle: Active; SizeAreaWB_mm2: 9.3; Green_REACh: Passed; U/M: EA; SizeZ_mm: 1.1; SizeX_mm: 2.1; SizeY_mm: 2.0; SizeArea_mm2: 4.2; CompType: IC

## Sheet TIDA-01586_Board2_Hardware.SchDoc: Hardware
size 431 x 279 mm; Date: Not shown in title block; ApprovedBy: Not shown in title block; CheckedBy: Not shown in title block; Author: Not shown in title block; CompanyName: Not shown in title block; DrawnBy: David Stout; Engineer: Not shown in title block; Organization: Not shown in title block; Address1: Not shown in title block; Address2: Not shown in title block; Address3: Not shown in title block; Address4: Not shown in title block; DocumentNumber: 1; Revision: Use project parameter SCH_Rev; SheetNumber: 4; SheetTotal: 4; PageSetup: Record=PageOptions¦CenterHorizontal=True¦CenterVertical=True¦PrintScale=1.00¦XCorrection=1.00¦YCorrection=1.00¦PrintKind=0¦BorderSize=5000000¦LeftOffset=0¦BottomOffset=0¦Orientation=2¦PaperLength=1000¦PaperWidth=1000¦Scale=100¦PaperSource=15¦PrintQuality=600¦MediaType=1¦DitherType=10¦PaperKind=Letter¦PrintScaleMode=1
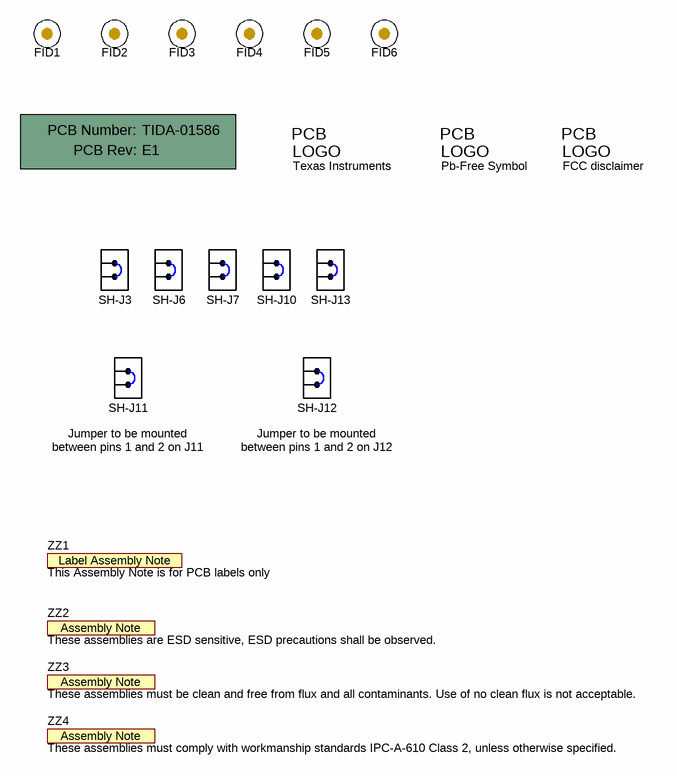
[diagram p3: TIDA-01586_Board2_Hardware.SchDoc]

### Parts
!PCB  Printed Circuit Board  (value not drawn)  (mechanical)
FID1  Fiducial  [Fiducial10-20]  (value not drawn)
FID2  Fiducial  [Fiducial10-20]  (value not drawn)
FID3  Fiducial  [Fiducial10-20]  (value not drawn)
FID4  Fiducial  [Fiducial10-20]  (value not drawn)
FID5  Fiducial  [Fiducial10-20]  (value not drawn)
FID6  Fiducial  [Fiducial10-20]  (value not drawn)
Logo1  Texas Instruments  [TI_Stacked_Overlay_Small]  (no BOM)
Logo2  Pb-Free Symbol  [Pb-Free_Overlay_Small]  (no BOM)
Logo3  FCC disclaimer  [FCC_disclaimer]  (no BOM)
SH-J3  SNT-100-BK-G  [SNT-100-BK-G]  (value not drawn)
SH-J6  SNT-100-BK-G  [SNT-100-BK-G]  (value not drawn)
SH-J7  SNT-100-BK-G  [SNT-100-BK-G]  (value not drawn)
SH-J10  SNT-100-BK-G  [SNT-100-BK-G]  (value not drawn)
SH-J11  SNT-100-BK-G  [SNT-100-BK-G]  (value not drawn)
SH-J12  SNT-100-BK-G  [SNT-100-BK-G]  (value not drawn)
SH-J13  SNT-100-BK-G  [SNT-100-BK-G]  (value not drawn)
ZZ1  This Assembly Note is for PCB labels only  [AssemblyNoteLabel]  (no BOM)
ZZ2  These assemblies are ESD sensitive, ESD precautions shall be observed.  [AssemblyNote]  (no BOM)
ZZ3  These assemblies must be clean and free from flux and all contaminants. Use of no clean flux is not acceptable.  [AssemblyNote]  (no BOM)
ZZ4  These assemblies must comply with workmanship standards IPC-A-610 Class 2, unless otherwise specified.  [AssemblyNote]  (no BOM)

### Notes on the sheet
- (near SH-J11) Jumper to be mounted
  between pins 1 and 2 on J11
- (near SH-J12) Jumper to be mounted
  between pins 1 and 2 on J12

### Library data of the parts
!PCB = CMP-0003618-2: Manufacturer: Any; PartNumber: TIDA-01586
FID1-FID3 = CMP-0077181-1: Fiducial mark.  There is nothing to buy or mount.
FID4-FID6 = Fiducial: Fiducial mark.  There is nothing to buy or mount.; SymbolCreator: codlsc
Logo1 = CMP-0074838-1: Texas Instrument Corporate Signature; SymbolCreator: a0412235; Lib Reference: TI_Logo; Library Reference: Logo
Logo2 = CMP-0074839-1: SymbolCreator: a0412235
Logo3 = CMP-0074847-1: FCC_disclaimer
SH-J3 SH-J6 SH-J7 SH-J10-SH-J13 = CMP-0003623-1: Shunt, 100mil, Gold plated, Black; Alternate PartNumber: 969102-0000-DA; Manufacturer: Samtec; Alternate Manufacturer: 3M; Value: 1x2; Note: You can "mate" this to a header by matching the designator.  i.e. use SH-J3 for header J3
ZZ1 = CMP-0003616-3
ZZ2 = CMP-0077236-1
ZZ3 = CMP-0077237-1
ZZ4 = CMP-0077238-1

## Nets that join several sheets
GND: TIDA-01586_Board2_Power (28 pins), TIDA-01586_Board2_MCU_Drivers (24 pins)
VCC_3V: TIDA-01586_Board2_Power (J7.1 R14.2 R16.2 TP10.1), TIDA-01586_Board2_MCU_Drivers (6 pins)
DRV_5V: TIDA-01586_Board2_Power (6 pins), TIDA-01586_Board2_MCU_Drivers (C12.1 C13.1 U3.1)
N12V_PRES: TIDA-01586_Board2_Power (R15.2), TIDA-01586_Board2_MCU_Drivers (J1.2)
VIN_5V: TIDA-01586_Board2_Power (8 pins), TIDA-01586_Board2_MCU_Drivers (J13.1)
VIN_12V: TIDA-01586_Board2_Power (10 pins), TIDA-01586_Board2_MCU_Drivers (J10.1)

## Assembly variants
001: not fitted FID1 FID2 FID3 FID4 FID5 FID6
